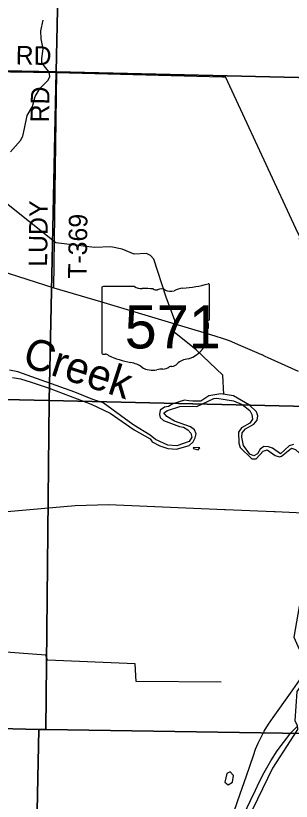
# Model space of a CAD drawing. Extents: x -784 to 1375, y -225 to 440.
# Drawn here: x 270.49 to 287.9, y 339.88 to 389.47 of the extents above; entities that cross this region are included whole.
import ezdxf

# ---------------------------------------------------------------- set-up
doc = ezdxf.new("R2010")
doc.units = 0
for name, color, linetype in [('GM_X_County_Road', 7, 'Continuous'), ('GM_X_County_Road_Text', 7, 'Continuous'), ('GM_X_Major_River', 7, 'Continuous'), ('GM_X_Major_River_Text', 7, 'Continuous'), ('GM_X_Minor_Lake', 7, 'Continuous'), ('GM_X_Minor_River', 7, 'Continuous'), ('GM_X_Rail_Line', 7, 'Continuous'), ('GM_X_Section', 7, 'Continuous'), ('GM_X_State_Location', 7, 'Continuous'), ('GM_X_State_Route', 7, 'Continuous'), ('GM_X_State_Shield', 7, 'Continuous'), ('GM_X_Township_Road', 7, 'Continuous'), ('GM_X_Township_Road_Text', 7, 'Continuous')]:
    doc.layers.add(name, color=color, linetype=linetype)

msp = doc.modelspace()

# ---------------------------------------------------------------- linework, layer by layer
at = {"layer": 'GM_X_County_Road'}
for points in [[(252.402, 386.288), (262.79, 386.043), (273.079, 385.889), (283.53, 385.61)], [(283.53, 385.61), (283.735, 385.605)]]:
    msp.add_lwpolyline(points, dxfattribs=at)
at = {"layer": 'GM_X_Major_River'}
for points in [[(278.976, 363.003), (277.947, 363.631), (277.655, 363.834), (276.011, 365.038), (275.35, 365.243), (274.219, 365.711), (270.611, 366.997), (270.089, 367.104)], [(270.294, 366.625), (270.793, 366.55), (271.461, 366.344), (272.611, 365.961), (275.247, 364.944), (276.461, 364.387), (277.977, 363.336), (278.977, 362.769)], [(287.211, 361.806), (286.716, 362.168), (286.451, 362.266), (286.169, 362.279), (285.923, 362.102), (285.769, 361.823), (285.532, 361.678), (285.275, 361.799), (284.884, 362.331), (284.776, 362.859), (284.804, 363.148), (285.012, 363.396), (285.535, 363.693), (285.75, 363.94), (285.779, 364.222), (285.705, 364.474), (285.265, 364.889), (284.248, 365.478), (283.45, 365.594), (282.688, 365.473), (282.188, 365.129), (281.687, 365.129), (281.428, 365.165), (281.147, 365.201), (280.414, 364.97), (280.145, 364.802), (279.877, 364.759), (279.616, 364.576), (279.564, 364.302), (279.608, 364.105), (279.824, 363.913), (280.829, 363.536), (281.087, 363.493), (281.351, 363.339), (281.551, 363.116), (281.617, 362.872), (281.456, 362.6), (280.659, 362.316), (280.088, 362.364), (279.31, 362.714), (278.976, 363.003)], [(278.977, 362.769), (279.104, 362.577), (279.601, 362.318), (280.107, 362.144), (280.64, 362.104), (281.451, 362.342), (281.69, 362.565), (281.828, 362.814), (281.879, 363.079), (281.782, 363.332), (281.526, 363.524), (280.529, 363.87), (280.032, 364.169), (279.84, 364.392), (280.085, 364.552), (280.858, 364.806), (281.658, 364.832), (281.924, 364.804), (282.999, 365.303), (283.195, 365.324), (284.243, 365.165), (284.795, 364.936), (285.275, 364.552), (285.411, 364.291), (285.438, 364.008), (285.277, 363.752), (284.746, 363.447), (284.554, 363.176), (284.574, 362.493), (284.671, 362.209), (285.403, 361.499), (285.67, 361.495), (286.117, 361.989), (286.377, 362.071), (286.881, 361.71), (287.146, 361.635), (287.278, 361.675)], [(288.037, 362.412), (287.769, 362.315), (287.211, 361.806)], [(287.278, 361.675), (287.907, 362.163), (288.165, 362.088), (288.674, 361.633), (289.035, 361.18), (289.323, 361.065), (290.025, 360.372), (290.551, 359.947), (291.754, 358.814), (292.293, 358.399)]]:
    msp.add_lwpolyline(points, dxfattribs=at)
at = {"layer": 'GM_X_Minor_Lake'}
for points in [[(282.122, 362.192), (281.723, 362.212), (281.706, 362.142)], [(281.706, 362.142), (282.011, 362.068), (282.122, 362.192)], [(284.039, 341.735), (283.827, 341.628), (283.703, 341.08), (283.904, 340.921)], [(283.904, 340.921), (284.18, 341.098), (284.24, 341.513), (284.039, 341.735)]]:
    msp.add_lwpolyline(points, dxfattribs=at)
at = {"layer": 'GM_X_Minor_River'}
for points in [[(270.148, 380.886), (270.787, 381.588), (270.94, 381.86), (271.051, 382.352), (271.213, 383.181), (271.544, 383.74), (271.712, 384.372), (272.034, 384.892), (272.544, 385.393), (272.635, 385.643), (272.6, 385.91), (272.147, 386.498), (272.144, 386.772), (272.225, 387.39), (272.094, 388.004), (272.072, 388.514), (272.232, 389.193)], [(283.628, 365.568), (283.572, 366.776), (281.882, 368.372), (280.506, 369.485), (280.534, 370.237), (279.987, 371.705), (279.22, 374.101), (278.997, 374.332), (278.748, 374.454), (277.979, 374.428), (277.216, 374.73), (276.49, 374.884), (275.47, 374.838), (273.029, 375.13), (269.688, 377.788)], [(288.558, 353.149), (288.058, 350.249), (288.753, 348.693), (289.169, 348.231), (288.902, 347.742), (288.243, 346.812), (288.118, 344.955), (288.262, 344.678), (288.281, 344.403), (286.703, 341.975), (278.796, 325.615), (278.65, 325.382)], [(283.465, 347.408), (278.087, 347.444), (278.035, 348.558), (272.49, 348.799), (272.385, 349.099), (268.729, 349.387), (267.982, 349.259), (266.122, 349.588), (265.83, 349.02), (265.503, 348.673), (265.179, 348.082), (263.455, 346.676), (262.952, 346.19), (262.709, 345.723), (262.449, 345.642), (261.281, 345.614), (260.131, 346.692), (259.811, 347.223), (258.736, 348.119), (258.283, 349.092), (258.374, 349.404), (258.464, 349.606), (258.466, 350.171), (258.306, 350.464)]]:
    msp.add_lwpolyline(points, dxfattribs=at)
at = {"layer": 'GM_X_Rail_Line'}
for points in [[(284.224, 339.068), (284.523, 339.931), (285.064, 341.489), (285.501, 342.77), (285.643, 343.173), (285.808, 343.553), (285.965, 343.894), (286.192, 344.304), (286.464, 344.757), (286.748, 345.171), (287.84, 346.697), (289.019, 348.383)], [(284.009, 337.198), (285.321, 339.923), (285.628, 340.583), (285.873, 341.078), (286.176, 341.692), (286.606, 342.436), (287.013, 343.062), (287.412, 343.599), (287.87, 344.193), (288.275, 344.604)]]:
    msp.add_lwpolyline(points, dxfattribs=at)
at = {"layer": 'GM_X_Section'}
for points in [[(273.347, 399.712), (273.043, 385.919), (252.384, 386.319), (252.836, 407.172), (264.746, 406.892)], [(294.035, 399.712), (293.747, 385.447), (273.043, 385.919), (273.347, 399.712)]]:
    msp.add_lwpolyline(points, dxfattribs=at)
for points in [[(252.384, 386.319), (273.043, 385.919), (272.601, 365.183), (251.944, 365.638)], [(273.043, 385.919), (293.747, 385.447), (293.485, 364.699), (272.601, 365.183)], [(251.944, 365.638), (272.601, 365.183), (272.386, 344.418), (271.941, 344.413), (251.519, 344.932)], [(272.601, 365.183), (293.485, 364.699), (293.008, 344.097), (292.781, 344.102), (272.386, 344.418)], [(251.519, 344.932), (271.941, 344.413), (271.521, 323.911), (250.93, 324.192), (251.254, 344.931)], [(272.386, 344.418), (292.781, 344.102), (292.404, 323.388), (271.521, 323.911), (271.941, 344.413)]]:
    msp.add_lwpolyline(points, close=True, dxfattribs=at)
at = {"layer": 'GM_X_State_Route'}
for points in [[(284.428, 384.117), (283.735, 385.605)], [(288.426, 375.358), (288.428, 375.519), (288.184, 376.044), (284.428, 384.117)], [(260.683, 376.179), (260.879, 376.115), (262.583, 375.566), (265.012, 374.801), (266.059, 374.478), (267.751, 373.933), (272.906, 372.299), (275.853, 371.426), (280.114, 370.154), (281.81, 369.646), (282.524, 369.428), (283.133, 369.243), (283.523, 369.122), (283.973, 368.966), (284.699, 368.656), (285.287, 368.391), (286.009, 368.089), (286.039, 368.075)], [(286.039, 368.075), (286.23, 367.988)], [(286.23, 367.988), (286.416, 367.904), (288.325, 367.035)], [(263.816, 357.614), (263.906, 357.575), (267.373, 357.914), (269.939, 358.164), (274.235, 358.56), (276.352, 358.618), (283.687, 358.302), (283.735, 358.3)], [(283.735, 358.3), (286.812, 358.168), (286.873, 358.165)], [(286.873, 358.165), (289.542, 358.05), (290.025, 357.952), (290.539, 357.83), (290.894, 357.601), (291.216, 357.311), (292.119, 356.183), (293.085, 354.976), (293.209, 355.076), (293.329, 355.173), (293.404, 355.233)]]:
    msp.add_lwpolyline(points, dxfattribs=at)
at = {"layer": 'GM_X_State_Shield'}
for p, q in [((282.733, 370.317), (282.733, 372.476)), ((275.936, 372.303), (275.936, 368.176)), ((277.993, 372.374), (276.002, 372.374)), ((282.733, 370.318), (282.733, 370.317))]:
    msp.add_line(p, q, dxfattribs=at)
for centre, major_axis, start_param, end_param in [((280.312, 378.001), (7.209, 0), 4.814394, 5.042369), ((282.658, 372.485), (0.0757, 0), 6.141152, 7.989035), ((276.013, 372.312), (0.0788, 0), 1.712693, 3.28349), ((278.467, 372.853), (0.764, 0), 4.042523, 4.731795), ((278.721, 370.057), (2.742, 0), 1.404758, 1.657858), ((279.343, 372.333), (0.22, 0), 3.836095, 5.185415), ((279.667, 371.856), (0.458, 0), 0.950623, 2.079405), ((280.258, 372.511), (0.551, 0), 4.081561, 5.145723), ((281.231, 371.113), (1.45, 0), 1.699011, 2.107814), ((282.716, 370.159), (0.117, 0), 1.883978, 3.671073), ((281.971, 369.886), (0.703, 0), 5.934695, 6.695948), ((282.652, 370.309), (0.081, 0), 5.05454, 6.418171), ((283.004, 369.414), (0.511, 0), 2.387724, 3.262537), ((280.716, 369.139), (1.803, 0), 5.101752, 6.440018), ((276.014, 368.167), (0.0794, 0), 3.00124, 4.508301), ((276.026, 368.589), (0.606, 0), 4.665946, 4.897461), ((276.15, 367.937), (0.219, 0), 0.519207, 1.627899), ((278.91, 371.646), (5.206, 0), 4.195997, 4.488961), ((277.358, 366.321), (1.629, 0), 0.823519, 1.323587), ((280.225, 367.776), (0.583, 0), 4.937069, 5.64225), ((281.476, 367.017), (0.988, 0), 1.647645, 2.488434), ((279.12, 367.917), (1.034, 0), 4.026481, 4.996735), ((279.717, 366.49), (0.849, 0), 1.495662, 1.94098), ((279.793, 367.608), (0.551, 0), 4.691044, 5.507374), ((280.291, 367.208), (0.155, 0), 1.147584, 2.315152)]:
    msp.add_ellipse(centre, major_axis=major_axis, ratio=0.8, start_param=start_param, end_param=end_param, dxfattribs=at)
at = {"layer": 'GM_X_Township_Road'}
msp.add_lwpolyline([(272.906, 372.299), (273.079, 385.889)], dxfattribs=at)

# ---------------------------------------------------------------- texts
at = {"layer": 'GM_X_County_Road_Text'}
msp.add_text('RD', height=1.1719, rotation=359.0128, dxfattribs=at).set_placement((270.479, 386.395))
at = {"layer": 'GM_X_Major_River_Text'}
msp.add_text('Creek', height=1.953, rotation=342.0322, dxfattribs=at).set_placement((270.824, 367.394))
at = {"layer": 'GM_X_State_Location'}
for s in ['s', 'r']:
    msp.add_text(s, height=0.00391, dxfattribs=at).set_placement((279.258, 369.965))
msp.add_text('571', height=0.00391, rotation=0, dxfattribs=at).set_placement((277.879, 369.681))
at = {"layer": 'GM_X_State_Shield'}
msp.add_text('571', height=2.7191, dxfattribs=at).set_placement((277.374, 368.467))
at = {"layer": 'GM_X_Township_Road_Text'}
for s, rotation, p in [('RD', 89.0123, (272.588, 382.728)), ('LUDY', 89.2559, (272.468, 373.617)), ('T-369', 89.1574, (274.963, 372.859))]:
    msp.add_text(s, height=1.1719, rotation=rotation, dxfattribs=at).set_placement(p)

doc.saveas('drawing.dxf')
